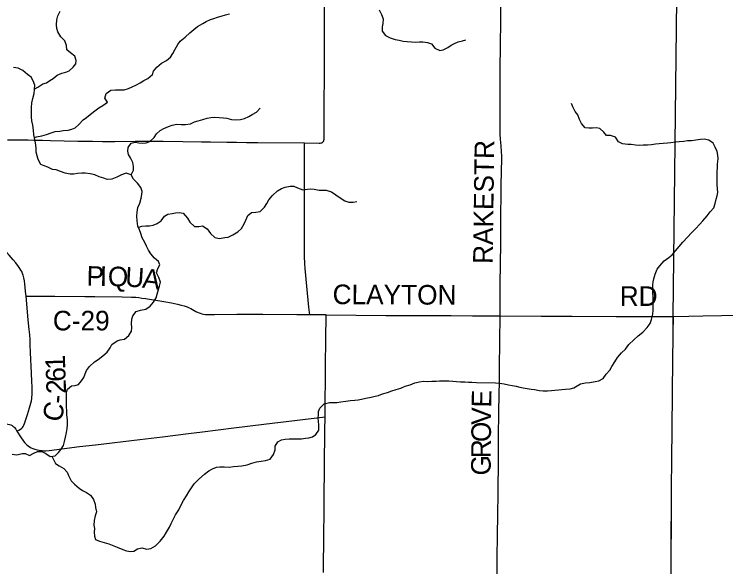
# Model space of a CAD drawing. Extents: x -87 to 2145, y -2128 to 440.
# Drawn here: x 31.9 to 86.3, y -1156 to -1113.7 of the extents above; entities that cross this region are included whole.
import ezdxf

# ---------------------------------------------------------------- set-up
doc = ezdxf.new("R2010")
doc.units = 0
for name, color, linetype in [('GM_X_County_Road', 7, 'Continuous'), ('GM_X_County_Road_Text', 7, 'Continuous'), ('GM_X_Minor_River', 7, 'Continuous'), ('GM_X_Township', 7, 'Continuous'), ('GM_X_Township_Road', 7, 'Continuous'), ('GM_X_Township_Text', 7, 'Continuous')]:
    doc.layers.add(name, color=color, linetype=linetype)

msp = doc.modelspace()

# ---------------------------------------------------------------- linework, layer by layer
at = {"layer": 'GM_X_County_Road'}
msp.add_line((54.455, -1136.699), (55.709, -1136.717), dxfattribs=at)
for points in [[(69.012, -1136.8), (69.028, -1134.356), (69.043, -1132.847), (69.066, -1131.239), (69.08, -1129.845), (69.111, -1126.778), (69.139, -1124.777), (69.142, -1124.565), (69.134, -1124.249), (69.101, -1123.798), (69.055, -1123.292), (69.029, -1122.898), (69.017, -1122.7), (69.011, -1122.505), (69.012, -1120.864), (69.027, -1118.764), (69.029, -1117.616), (69.045, -1116.452), (69.064, -1113.911), (69.073, -1113.435), (69.114, -1110.249)], [(32.759, -1135.307), (32.725, -1134.93), (32.694, -1134.613), (32.664, -1134.375), (32.628, -1134.13), (32.58, -1133.887), (32.53, -1133.695), (32.483, -1133.554), (32.426, -1133.415), (32.365, -1133.297), (32.294, -1133.184), (32.178, -1133.024), (31.963, -1132.753), (31.761, -1132.516), (31.462, -1132.167), (31.256, -1131.938), (31.064, -1131.737), (30.781, -1131.454), (30.36, -1131.063), (30.17, -1130.903), (30.15, -1130.888)], [(32.688, -1144.909), (32.697, -1144.883), (32.865, -1144.351), (33.016, -1143.849), (33.122, -1143.469), (33.164, -1143.292), (33.193, -1143.13), (33.21, -1143.015), (33.227, -1142.835), (33.235, -1142.653), (33.235, -1142.472), (33.225, -1142.226), (33.206, -1141.833), (33.176, -1141.194), (33.103, -1139.605), (33.077, -1138.983), (33.06, -1138.606), (33.038, -1138.246), (33.003, -1137.853), (32.928, -1137.102), (32.759, -1135.307)], [(32.759, -1135.307), (34.956, -1135.294), (37.265, -1135.314), (38.019, -1135.318), (40.114, -1135.34), (40.812, -1135.367), (41.143, -1135.386), (41.393, -1135.411), (41.621, -1135.438), (41.892, -1135.484), (43.292, -1135.709), (43.872, -1135.819), (44.337, -1135.912), (44.623, -1135.979), (44.859, -1136.044), (45.074, -1136.114), (45.239, -1136.182), (45.368, -1136.248), (45.753, -1136.465), (45.916, -1136.546), (46.07, -1136.606), (46.214, -1136.647), (46.343, -1136.674), (46.491, -1136.694), (46.64, -1136.703), (46.87, -1136.699), (47.165, -1136.694), (48.887, -1136.671), (50.871, -1136.667), (53.479, -1136.693), (54.455, -1136.699)], [(82.272, -1136.857), (83.455, -1136.837), (84.537, -1136.813), (87.372, -1136.739), (88.807, -1136.702), (90.193, -1136.677), (91.046, -1136.652), (91.927, -1136.622), (94.34, -1136.539), (96.135, -1136.485), (97.689, -1136.448), (99.056, -1136.413), (100.938, -1136.374), (102.691, -1136.339), (103.997, -1136.32), (105.942, -1136.274), (108.249, -1136.251), (108.38, -1136.249)], [(55.709, -1136.717), (58.007, -1136.745), (60.271, -1136.764), (65.274, -1136.786), (66.914, -1136.792), (69.012, -1136.8)], [(68.679, -1172.7), (68.718, -1169.422), (68.71, -1165.486), (68.712, -1163.353), (68.717, -1162.5), (68.72, -1161.943), (68.764, -1158.711), (68.772, -1157.776), (68.803, -1155.546), (68.832, -1153.348), (68.845, -1152.249), (68.87, -1150.166), (68.891, -1147.985), (68.906, -1145.492), (68.916, -1144.721), (68.926, -1143.967), (68.935, -1143.031), (68.962, -1141.621), (68.979, -1140.785), (68.998, -1138.751), (69.012, -1136.8)], [(69.012, -1136.8), (72.147, -1136.819), (74.526, -1136.83), (77.906, -1136.851), (80.727, -1136.864), (82.272, -1136.857)], [(31.118, -1145.032), (31.267, -1145.056), (31.362, -1145.078), (31.481, -1145.108), (31.585, -1145.143), (31.686, -1145.191), (31.755, -1145.233), (31.818, -1145.284), (31.88, -1145.352), (31.972, -1145.471), (32.063, -1145.616)], [(32.063, -1145.616), (32.205, -1145.545), (32.338, -1145.469), (32.429, -1145.397), (32.486, -1145.334), (32.534, -1145.265), (32.59, -1145.162), (32.642, -1145.039), (32.688, -1144.909)]]:
    msp.add_lwpolyline(points, dxfattribs=at)
at = {"layer": 'GM_X_Minor_River'}
for points in [[(33.417, -1119.453), (33.651, -1119.317), (34.039, -1119.064), (34.312, -1118.989), (34.567, -1118.814), (34.832, -1118.638), (35.149, -1118.404), (35.505, -1118.23), (35.798, -1118.166), (36.061, -1118.072), (36.359, -1117.786), (36.556, -1117.529), (36.602, -1117.278), (36.478, -1116.933), (36.152, -1116.684), (35.875, -1116.456), (35.852, -1116.134), (35.719, -1115.768), (35.414, -1115.46), (35.191, -1115.082), (35.117, -1114.819), (35.082, -1114.556), (35.101, -1114.164), (35.188, -1113.854), (35.366, -1113.505)], [(59.762, -1113.388), (59.936, -1113.744), (60.069, -1114.089), (60.041, -1114.441), (59.995, -1114.701), (59.988, -1115.033), (60.242, -1115.371), (60.6, -1115.55), (60.98, -1115.659), (61.3, -1115.727), (61.611, -1115.785), (61.911, -1115.822)], [(33.404, -1123.171), (33.569, -1123.112), (33.963, -1123.03), (34.327, -1122.928), (34.672, -1122.804), (34.985, -1122.711), (35.348, -1122.668), (35.6, -1122.634), (35.973, -1122.602), (36.256, -1122.537), (36.51, -1122.422), (36.787, -1122.177), (37.136, -1121.812), (37.392, -1121.636), (37.658, -1121.411), (38.006, -1121.126), (38.333, -1120.902), (38.639, -1120.707), (38.985, -1120.473), (38.781, -1120.147), (38.88, -1119.786), (39.237, -1119.542), (39.6, -1119.51), (39.871, -1119.506), (40.263, -1119.505), (40.597, -1119.412), (40.881, -1119.297), (41.197, -1119.123), (41.482, -1118.969), (41.756, -1118.814), (42.082, -1118.65), (42.43, -1118.356), (42.516, -1118.096), (42.764, -1117.779), (43.123, -1117.485), (43.499, -1117.282), (43.796, -1117.027), (43.994, -1116.73), (44.151, -1116.411), (44.361, -1116.043), (44.547, -1115.786), (44.916, -1115.482), (45.295, -1115.169), (45.582, -1114.894), (45.879, -1114.669), (46.276, -1114.436), (46.53, -1114.301), (46.865, -1114.138), (47.128, -1114.063), (47.412, -1113.969), (47.685, -1113.895), (48.019, -1113.792), (48.323, -1113.708)], [(61.911, -1115.822), (62.253, -1115.85), (62.514, -1115.876), (62.846, -1115.854), (63.097, -1115.85), (63.468, -1115.908), (63.778, -1116.006), (64.032, -1116.334), (64.4, -1116.514), (64.663, -1116.459), (65.009, -1116.276), (65.264, -1116.091), (65.538, -1115.967), (65.812, -1115.853), (66.136, -1115.76), (66.399, -1115.686)], [(41.538, -1126.997), (41.285, -1126.649), (40.969, -1126.359), (40.796, -1126.013), (40.416, -1125.894), (40.052, -1126.017), (39.696, -1126.19), (39.321, -1126.343), (38.968, -1126.365), (38.699, -1126.279), (38.339, -1126.16), (38.02, -1126.022), (37.66, -1125.943), (37.289, -1125.895), (37.028, -1125.889), (36.685, -1125.922), (36.413, -1125.956), (36.121, -1125.969), (35.761, -1125.901), (35.392, -1125.752), (35.062, -1125.644), (34.771, -1125.617), (34.413, -1125.438), (34.154, -1125.341), (33.885, -1125.215), (33.692, -1124.848), (33.598, -1124.553), (33.534, -1124.28), (33.52, -1123.957), (33.469, -1123.563), (33.434, -1123.311), (33.361, -1122.967), (33.328, -1122.613), (33.277, -1122.219), (33.203, -1121.895), (33.179, -1121.613), (33.167, -1121.24), (33.175, -1120.877), (33.193, -1120.505), (33.271, -1120.175), (33.39, -1119.794), (33.416, -1119.503), (33.423, -1119.171), (33.31, -1118.836), (33.145, -1118.56), (32.858, -1118.343), (32.503, -1118.032), (32.145, -1117.863), (31.804, -1117.805)], [(85.626, -1125.797), (85.643, -1125.456), (85.649, -1125.195), (85.688, -1124.793), (85.684, -1124.512), (85.619, -1124.239), (85.466, -1123.913), (85.311, -1123.608), (84.985, -1123.369), (84.624, -1123.3), (84.342, -1123.313), (84, -1123.355), (83.647, -1123.407), (83.365, -1123.43), (83.082, -1123.463), (82.71, -1123.495), (82.448, -1123.518), (82.085, -1123.56), (81.833, -1123.584), (81.49, -1123.626), (81.188, -1123.649), (80.916, -1123.683), (80.593, -1123.715), (80.291, -1123.738), (79.959, -1123.75), (79.677, -1123.764), (79.386, -1123.747), (79.035, -1123.698), (78.784, -1123.692), (78.392, -1123.653), (78.084, -1123.505), (77.851, -1123.127), (77.471, -1123.017), (77.16, -1123), (76.944, -1122.743), (76.648, -1122.485), (76.358, -1122.428), (76.076, -1122.441), (75.804, -1122.455), (75.523, -1122.418), (75.249, -1122.09), (75.095, -1121.784), (74.952, -1121.419), (74.756, -1121.163), (74.573, -1120.816), (74.488, -1120.563)], [(40.828, -1126.077), (40.827, -1125.974), (40.964, -1125.664), (40.97, -1125.372), (40.937, -1125.069), (40.743, -1124.713), (40.598, -1124.458), (40.553, -1124.205), (40.579, -1123.933), (40.798, -1123.596), (41.091, -1123.512), (41.382, -1123.558), (41.643, -1123.584), (41.955, -1123.561), (42.228, -1123.467), (42.557, -1123.162), (42.744, -1122.884), (43.011, -1122.628), (43.306, -1122.463), (43.641, -1122.33), (43.935, -1122.226), (44.288, -1122.143), (44.619, -1122.171), (44.951, -1122.168), (45.325, -1122.106), (45.639, -1121.972), (45.913, -1121.888), (46.267, -1121.775), (46.611, -1121.692), (46.894, -1121.628), (47.165, -1121.614), (47.517, -1121.642), (47.848, -1121.659), (48.119, -1121.696), (48.479, -1121.784), (48.79, -1121.801), (49.173, -1121.78), (49.456, -1121.716), (49.791, -1121.552), (50.066, -1121.397), (50.382, -1121.213), (50.669, -1120.928)], [(59.452, -1142.953), (59.714, -1142.888), (60.018, -1142.774), (60.403, -1142.652), (60.737, -1142.548), (61.071, -1142.445), (61.416, -1142.322), (61.761, -1142.188), (62.135, -1142.066), (62.49, -1141.933), (62.864, -1141.861), (63.136, -1141.806), (63.468, -1141.814), (63.79, -1141.801), (64.122, -1141.788), (64.384, -1141.774), (64.716, -1141.771), (65.088, -1141.77), (65.409, -1141.787), (65.69, -1141.814), (65.991, -1141.84), (66.333, -1141.848), (66.604, -1141.864), (66.865, -1141.87), (67.217, -1141.888), (68.654, -1141.921), (68.985, -1141.949), (69.326, -1141.997), (69.656, -1142.075), (69.936, -1142.141), (70.237, -1142.189), (70.517, -1142.255), (70.787, -1142.312), (71.388, -1142.406), (71.639, -1142.442), (72.04, -1142.512), (72.301, -1142.528), (72.642, -1142.546), (72.954, -1142.512), (73.206, -1142.488), (73.488, -1142.464), (73.75, -1142.44), (74.023, -1142.406), (74.375, -1142.384), (74.658, -1142.299), (74.923, -1142.165), (75.178, -1141.989), (75.541, -1141.927), (75.894, -1141.905), (76.298, -1141.823), (76.57, -1141.769), (76.896, -1141.595), (77.144, -1141.269), (77.412, -1140.953), (77.569, -1140.674), (77.788, -1140.327), (78.006, -1140), (78.316, -1139.624), (78.614, -1139.339), (78.873, -1139.003), (79.243, -1138.629), (79.591, -1138.324), (79.939, -1138.061), (80.268, -1137.706), (80.496, -1137.389), (80.604, -1137.069), (80.703, -1136.679), (80.72, -1136.357), (80.717, -1136.015), (80.714, -1135.723), (80.722, -1135.341), (80.709, -1135.018), (80.695, -1134.726), (80.711, -1134.464), (80.726, -1134.213), (80.772, -1133.963), (80.87, -1133.602), (81.029, -1133.224), (81.236, -1132.967), (81.576, -1132.592), (81.924, -1132.339), (82.189, -1132.134), (82.437, -1131.828), (82.716, -1131.502), (83.005, -1131.157), (83.365, -1130.793), (83.664, -1130.458), (83.993, -1130.124), (84.281, -1129.809), (84.529, -1129.533), (84.849, -1129.158), (85.097, -1128.852), (85.365, -1128.537), (85.462, -1128.217), (85.55, -1127.887), (85.616, -1127.617), (85.672, -1127.367), (85.648, -1127.085), (85.615, -1126.752), (85.627, -1126.18), (85.626, -1125.797)], [(40.059, -1126.112), (40.054, -1126.116)], [(31.695, -1147.375), (32.056, -1147.423), (32.45, -1147.341), (32.702, -1147.327), (33.01, -1147.475), (33.346, -1147.301), (33.63, -1147.186), (33.962, -1147.173), (34.28, -1147.341), (34.597, -1147.56), (34.98, -1147.518), (35.227, -1147.261), (35.444, -1146.994), (35.631, -1146.726), (35.708, -1146.405), (35.776, -1146.074), (35.854, -1145.723), (35.89, -1145.422), (35.917, -1145.13), (35.925, -1144.767), (35.873, -1144.383), (35.87, -1144.061), (35.856, -1143.758), (35.852, -1143.496), (35.858, -1143.184), (35.854, -1142.922), (35.85, -1142.65), (35.916, -1142.399), (36.232, -1142.164), (36.505, -1142.13), (36.768, -1142.045), (37.005, -1141.768), (37.172, -1141.51), (37.278, -1141.24), (37.374, -1140.97), (37.602, -1140.683), (37.992, -1140.319), (38.267, -1140.143), (38.635, -1139.859), (38.953, -1139.584), (39.201, -1139.247), (39.328, -1138.988), (39.716, -1138.704), (39.969, -1138.639), (40.292, -1138.586), (40.619, -1138.311), (40.817, -1137.983), (40.854, -1137.712), (40.821, -1137.378), (40.838, -1137.046), (40.914, -1136.796), (41.172, -1136.479), (41.516, -1136.376), (41.91, -1136.304), (42.247, -1136.06), (42.505, -1135.763), (42.713, -1135.435), (42.799, -1135.145), (42.898, -1134.795), (42.974, -1134.534), (43.051, -1134.224), (42.918, -1133.868), (42.744, -1133.512), (42.842, -1133.171), (42.989, -1132.902), (42.894, -1132.648), (42.588, -1132.38), (42.293, -1132.061), (42.119, -1131.775), (41.974, -1131.479), (41.85, -1131.185), (41.646, -1130.837), (41.533, -1130.513), (41.428, -1130.218), (41.303, -1129.953), (41.262, -1129.539), (41.24, -1129.176), (41.266, -1128.875), (41.304, -1128.523), (41.462, -1128.184), (41.561, -1127.793), (41.617, -1127.532), (41.633, -1127.281), (41.538, -1126.997)], [(41.344, -1130.038), (41.625, -1129.94), (41.917, -1129.927), (42.199, -1129.923), (42.481, -1129.879), (42.776, -1129.744), (43.092, -1129.53), (43.341, -1129.183), (43.606, -1129.027), (43.929, -1128.984), (44.181, -1128.929), (44.463, -1128.905), (44.764, -1128.953), (45.108, -1129.323), (45.292, -1129.639), (45.647, -1129.96), (45.979, -1129.967), (46.251, -1129.923), (46.618, -1130.142), (46.872, -1130.501), (47.187, -1130.8), (47.557, -1130.889), (47.971, -1130.817), (48.223, -1130.783), (48.579, -1130.619), (48.956, -1130.386), (49.233, -1130.13), (49.452, -1129.753), (49.569, -1129.473), (49.727, -1129.134), (50.014, -1128.889), (50.346, -1128.876), (50.659, -1128.833), (50.988, -1128.488), (51.175, -1128.22), (51.332, -1127.931), (51.62, -1127.605), (51.98, -1127.231), (52.286, -1127.056), (52.589, -1126.963), (52.963, -1126.88), (53.244, -1126.897), (53.513, -1127.024), (53.932, -1127.174), (54.275, -1127.121), (54.547, -1127.097), (54.808, -1127.113), (55.168, -1127.202), (55.45, -1127.198), (55.702, -1127.184), (56.111, -1127.314), (56.448, -1127.543), (56.785, -1127.782), (57.132, -1128.012), (57.451, -1128.12), (57.773, -1128.107), (58.055, -1128.063)], [(34.742, -1147.544), (35.018, -1148.083), (35.296, -1148.271), (35.643, -1148.48), (35.898, -1148.768), (35.993, -1149.022), (36.196, -1149.409), (36.451, -1149.687), (36.817, -1149.977), (37.075, -1150.154), (37.383, -1150.312), (37.68, -1150.521), (37.924, -1150.858), (38.047, -1151.194), (38.082, -1151.447), (38.135, -1151.78), (38.038, -1152.091), (37.96, -1152.452), (37.952, -1152.804), (37.987, -1153.057), (37.971, -1153.339), (37.984, -1153.651), (38.079, -1153.906), (38.368, -1154.033), (38.738, -1154.142), (39.098, -1154.23), (39.476, -1154.38), (39.735, -1154.496), (40.154, -1154.677), (40.433, -1154.784), (40.744, -1154.821), (41.006, -1154.797), (41.281, -1154.631), (41.624, -1154.548), (42.004, -1154.647), (42.307, -1154.594), (42.654, -1154.38), (43.013, -1154.045), (43.313, -1153.658), (43.501, -1153.35), (43.73, -1152.952), (43.867, -1152.683), (44.004, -1152.384), (44.193, -1152.015), (44.432, -1151.647), (44.601, -1151.298), (44.79, -1150.92), (45.019, -1150.562), (45.207, -1150.254), (45.622, -1149.658), (45.971, -1149.293), (46.412, -1148.92), (46.74, -1148.645), (47.014, -1148.51), (47.328, -1148.386), (47.58, -1148.361), (47.922, -1148.359), (48.294, -1148.367), (48.617, -1148.334), (48.959, -1148.311), (49.261, -1148.278), (49.665, -1148.206), (50.02, -1148.063), (50.394, -1147.97), (50.747, -1147.908), (51.08, -1147.865), (51.424, -1147.761), (51.673, -1147.414), (51.802, -1147.044), (51.818, -1146.772), (52.026, -1146.445), (52.291, -1146.279), (52.584, -1146.225), (52.875, -1146.212), (53.177, -1146.198), (53.509, -1146.216), (53.831, -1146.203), (54.123, -1146.169), (54.386, -1146.124), (54.658, -1146.06), (54.924, -1145.874), (55.152, -1145.547), (55.161, -1145.144), (55.126, -1144.881), (55.092, -1144.629), (55.117, -1144.377), (55.133, -1144.126), (55.219, -1143.855), (55.568, -1143.541), (55.962, -1143.439), (56.234, -1143.425), (56.525, -1143.421), (56.848, -1143.378), (57.221, -1143.336), (57.574, -1143.283), (57.917, -1143.241), (58.169, -1143.216), (58.421, -1143.181), (58.744, -1143.108), (59.158, -1143.027), (59.452, -1142.953)]]:
    msp.add_lwpolyline(points, dxfattribs=at)
at = {"layer": 'GM_X_Township'}
msp.add_lwpolyline([(82.098, -1157.427), (82.101, -1154.655), (82.114, -1153.096), (82.12, -1151.866), (82.128, -1150.356), (82.151, -1147.4), (82.168, -1145.779), (82.201, -1142.379), (82.221, -1140.463), (82.249, -1138.114), (82.266, -1136.843), (82.556, -1110.367)], dxfattribs=at)
at = {"layer": 'GM_X_Township_Road'}
msp.add_line((55.709, -1136.717), (54.455, -1136.699), dxfattribs=at)
for points in [[(54.054, -1123.565), (55.177, -1123.595), (55.262, -1123.592), (55.33, -1123.581), (55.38, -1123.564), (55.427, -1123.54), (55.469, -1123.506), (55.502, -1123.463), (55.526, -1123.414), (55.541, -1123.363), (55.554, -1123.301), (55.558, -1123.236), (55.56, -1123.163), (55.552, -1121.817), (55.557, -1121.325), (55.564, -1120.456), (55.57, -1119.784), (55.576, -1119.259), (55.585, -1118.193), (55.596, -1115.322), (55.598, -1113.782), (55.606, -1112.519)], [(31.335, -1123.338), (31.876, -1123.341), (32.171, -1123.343), (32.662, -1123.346), (32.908, -1123.35), (33.35, -1123.358), (34.023, -1123.374), (34.629, -1123.393), (36.713, -1123.432), (37.828, -1123.45), (38.615, -1123.462), (39.223, -1123.467), (39.551, -1123.463), (41.109, -1123.453), (42.208, -1123.437), (42.568, -1123.432), (42.879, -1123.434), (43.254, -1123.439), (44.742, -1123.46), (46.168, -1123.483), (46.529, -1123.492), (46.874, -1123.489), (48.118, -1123.508), (48.446, -1123.524), (48.856, -1123.53), (49.627, -1123.54), (50.497, -1123.545), (54.054, -1123.565)], [(54.455, -1136.699), (54.438, -1136.534), (54.396, -1136.127), (54.239, -1134.528), (54.113, -1133.189), (54.088, -1132.83), (54.06, -1132.24), (54.051, -1131.815), (54.056, -1129.142), (54.052, -1127.354), (54.05, -1125.78), (54.054, -1123.565)], [(55.628, -1144.52), (55.642, -1143.514), (55.666, -1141.513), (55.671, -1140.578), (55.694, -1138.643), (55.709, -1136.717)], [(82.076, -1168.703), (82.084, -1168.236), (82.089, -1167.383), (82.09, -1166.662), (82.092, -1165.119), (82.09, -1163.461), (82.092, -1162.806), (82.097, -1162.019), (82.097, -1160.998), (82.104, -1157.441), (82.107, -1154.669), (82.12, -1153.11), (82.126, -1151.88), (82.135, -1150.371), (82.157, -1147.415), (82.174, -1145.793), (82.207, -1142.393), (82.227, -1140.477), (82.255, -1138.129), (82.272, -1136.857)], [(32.063, -1145.616), (32.382, -1146.128), (32.51, -1146.316), (32.647, -1146.498), (32.732, -1146.595), (32.813, -1146.673), (32.914, -1146.753), (33.022, -1146.825), (33.136, -1146.885), (33.285, -1146.949), (33.422, -1146.996), (33.595, -1147.042), (33.752, -1147.075), (33.883, -1147.099), (33.995, -1147.113), (34.108, -1147.118), (34.27, -1147.115), (34.514, -1147.097), (35.491, -1146.979), (36.841, -1146.806), (38.062, -1146.668), (41.464, -1146.271), (43.188, -1146.049), (45.174, -1145.807), (46.248, -1145.671), (48.656, -1145.357), (50.952, -1145.075), (55.628, -1144.52)], [(55.514, -1156.421), (55.521, -1155.339), (55.527, -1154.486), (55.54, -1153.584), (55.558, -1151.796), (55.568, -1150.91), (55.621, -1145.564), (55.628, -1144.52)]]:
    msp.add_lwpolyline(points, dxfattribs=at)
at = {"layer": 'GM_X_Township_Text'}
msp.add_lwpolyline([(82.098, -1157.427), (82.101, -1154.655), (82.114, -1153.096), (82.12, -1151.866), (82.128, -1150.356), (82.151, -1147.4), (82.168, -1145.779), (82.201, -1142.379), (82.221, -1140.463), (82.249, -1138.114), (82.266, -1136.843), (82.556, -1110.367)], dxfattribs=at)

# ---------------------------------------------------------------- texts
at = {"layer": 'GM_X_County_Road_Text'}
for s, rotation, p in [('RAKESTR', 89.2505, (68.45, -1132.839)), ('P', 358.9736, (37.375, -1134.496)), ('I', 358.9696, (38.387, -1134.515)), ('Q', 358.6594, (39.001, -1134.526)), ('U', 356.3073, (40.304, -1134.556)), ('A', 352.8305, (41.598, -1134.639)), ('CLAYTON', 359.7124, (56.204, -1135.905)), ('RD', 0, (78.17, -1136.042)), ('C-29', 0, (34.808, -1137.917)), ('1', 91.9894, (35.763, -1140.893)), ('6', 91.9154, (35.794, -1141.819)), ('2', 91.9573, (35.825, -1142.742)), ('-', 84.4097, (35.758, -1143.571)), ('E', 88.6885, (68.334, -1143.827)), ('C', 75.41, (35.403, -1145.016)), ('V', 89.5519, (68.324, -1145.141)), ('O', 89.5774, (68.314, -1146.461)), ('R', 89.5831, (68.305, -1147.693)), ('G', 89.5774, (68.296, -1149.013))]:
    msp.add_text(s, height=1.5, rotation=rotation, dxfattribs=at).set_placement(p)

doc.saveas('drawing.dxf')
